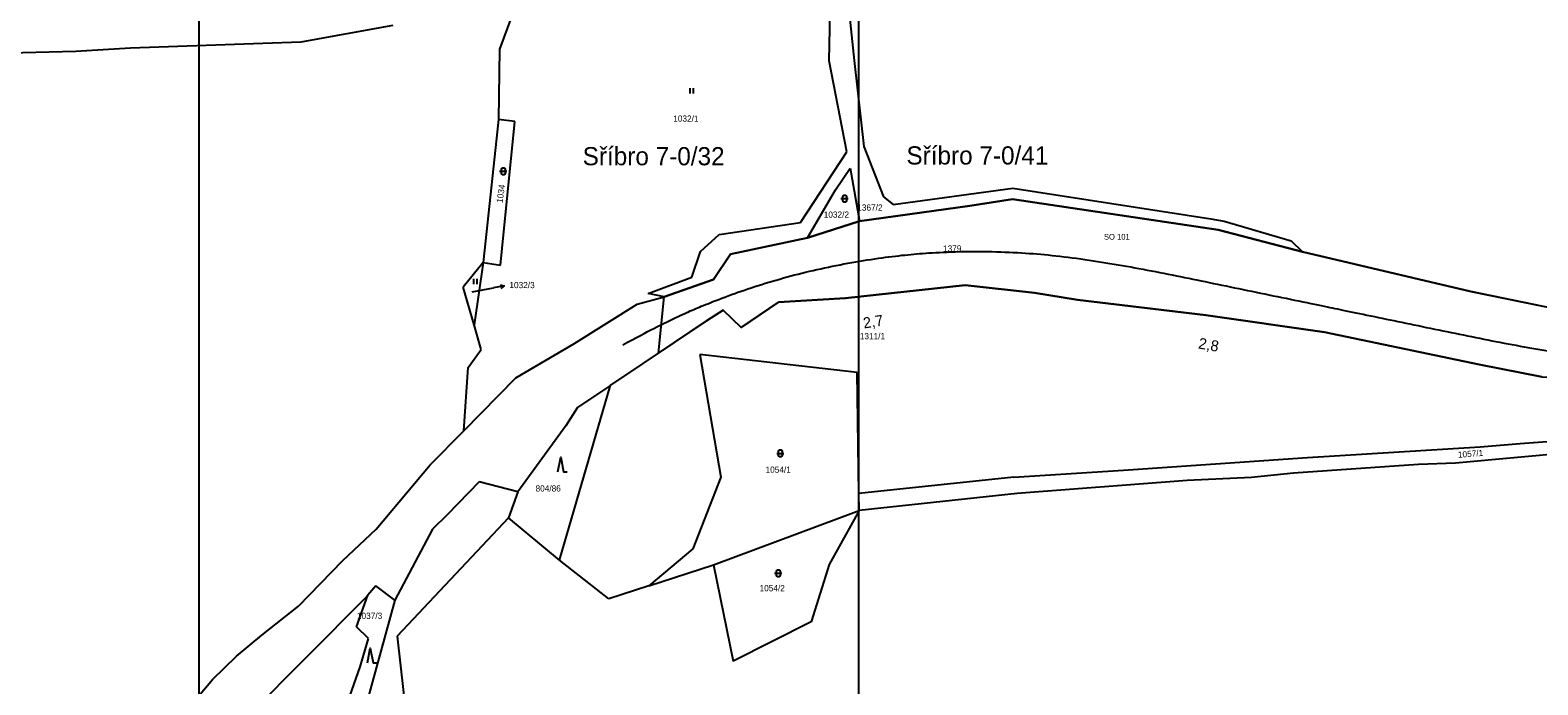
# Model space of a CAD drawing. Extents: x -852001 to -842497, y -1063614 to -1052182.
# Drawn here: x -843977.7 to -843563.3, y -1061386 to -1061205.9 of the extents above; entities that cross this region are included whole.
import ezdxf

# ---------------------------------------------------------------- set-up
doc = ezdxf.new("R2010")
doc.units = 0
for name, color, linetype in [('Default', 7, 'Continuous'), ('KLADY_ZMVM', 7, 'Continuous'), ('KN_HRANICE', 7, 'Continuous'), ('KN_KULTURY', 7, 'Continuous'), ('KN_PARCELY', 7, 'Continuous'), ('LEGENDA', 7, 'Continuous'), ('obvod_stavby', 7, 'Continuous'), ('so', 7, 'Continuous'), ('Vrstva 7', 7, 'Continuous'), ('Železniční svršek', 7, 'Continuous')]:
    doc.layers.add(name, color=color, linetype=linetype)

# ---------------------------------------------------------------- blocks, each defined once
blk = doc.blocks.new('306')
at = {"layer": 'Default'}
for p, q in [((-0.5, 1.5), (-0.5, 0)), ((0.5, 0), (0.5, 1.5))]:
    blk.add_line(p, q, dxfattribs=at)
blk = doc.blocks.new('308')
at = {"layer": 'Default'}
blk.add_lwpolyline([(-0.75, 0), (0, 4), (0.75, 0), (1.75, 0)], dxfattribs=at)
blk = doc.blocks.new('316')
at = {"layer": 'Default'}
for points in [[(-1, 1), (0.27, 1), (1, 1)], [(-0.5, 1.5), (-0.4, 1.79), (-0.15, 1.97), (0.16, 1.97), (0.41, 1.79), (0.51, 1.5), (0.51, 0.5), (0.41, 0.21), (0.16, 0.03), (-0.15, 0.03), (-0.4, 0.21), (-0.5, 0.5), (-0.5, 1.5)]]:
    blk.add_lwpolyline(points, dxfattribs=at)
blk = doc.blocks.new('10292')
at = {"layer": 'Default'}
blk.add_line((0, 3), (0, 0), dxfattribs=at)
blk.add_lwpolyline([(-0.5, 2), (0, 3), (0.5, 2)], dxfattribs=at)

msp = doc.modelspace()

# ---------------------------------------------------------------- linework, layer by layer
at = {"layer": 'KLADY_ZMVM'}
msp.add_line((-843750, -1061000), (-843750, -1061500), dxfattribs=at)
at = {"layer": 'KN_HRANICE'}
for p, q in [((-843758.11, -1061214.34), (-843757.44, -1061183.54)), ((-843842.44, -1061194.12), (-843848.69, -1061211.1)), ((-843752.83, -1061198.6), (-843751.24, -1061214.26)), ((-843878, -1061204.64), (-843903.31, -1061209.15)), ((-843903.31, -1061209.15), (-843950.16, -1061210.8)), ((-843965.16, -1061211.72), (-844011.33, -1061212.96)), ((-843950.16, -1061210.8), (-843965.16, -1061211.72)), ((-843848.69, -1061211.1), (-843848.99, -1061230.47)), ((-843753.24, -1061239.32), (-843758.11, -1061214.34)), ((-843751.24, -1061214.26), (-843748.59, -1061237.93)), ((-843848.99, -1061230.47), (-843853.2, -1061269.79)), ((-843844.45, -1061231.05), (-843848.99, -1061230.47)), ((-843848.42, -1061270.5), (-843844.45, -1061231.05)), ((-843748.59, -1061237.93), (-843743.16, -1061251.77)), ((-843765.97, -1061258.82), (-843753.24, -1061239.32)), ((-843756.33, -1061249.86), (-843752.32, -1061243.82)), ((-843752.32, -1061243.82), (-843749.69, -1061258.46)), ((-843763.99, -1061263.04), (-843756.33, -1061249.86)), ((-843740.51, -1061253.88), (-843707.55, -1061249.34)), ((-843707.55, -1061249.34), (-843653.11, -1061257.75)), ((-843749.69, -1061258.46), (-843719.38, -1061254.23)), ((-843743.16, -1061251.77), (-843740.51, -1061253.88)), ((-843719.38, -1061254.23), (-843707.71, -1061252.4)), ((-843707.71, -1061252.4), (-843651.14, -1061260.86)), ((-843788.34, -1061262.14), (-843765.97, -1061258.82)), ((-843763.99, -1061263.04), (-843749.69, -1061258.46)), ((-843653.11, -1061257.75), (-843649.46, -1061258.41)), ((-843649.46, -1061258.41), (-843631.1, -1061263.83)), ((-843793.44, -1061266.79), (-843788.34, -1061262.14)), ((-843785.22, -1061267.47), (-843763.99, -1061263.04)), ((-843651.14, -1061260.86), (-843627.97, -1061266.91)), ((-843795.86, -1061273.88), (-843793.44, -1061266.79)), ((-843631.1, -1061263.83), (-843627.97, -1061266.91)), ((-843627.97, -1061266.91), (-843581.64, -1061277.78)), ((-843853.2, -1061269.79), (-843858.65, -1061276.59)), ((-843853.2, -1061269.79), (-843855.66, -1061286.98)), ((-843853.2, -1061269.79), (-843848.42, -1061270.5)), ((-843789.91, -1061274.45), (-843785.22, -1061267.47)), ((-843807.87, -1061278.34), (-843795.86, -1061273.88)), ((-843803.41, -1061279.25), (-843789.91, -1061274.45)), ((-843855.66, -1061286.98), (-843858.65, -1061276.59)), ((-843810.84, -1061281.31), (-843803.41, -1061279.25)), ((-843803.41, -1061279.25), (-843807.87, -1061278.34)), ((-843753.6, -1061279.61), (-843772.02, -1061280.75)), ((-843720.66, -1061276.06), (-843753.6, -1061279.61)), ((-843701.61, -1061278.11), (-843720.66, -1061276.06)), ((-843689.83, -1061280.06), (-843701.61, -1061278.11)), ((-843581.64, -1061277.78), (-843550.13, -1061284.28)), ((-843828.23, -1061292.19), (-843810.84, -1061281.31)), ((-843787.23, -1061282.93), (-843791.76, -1061285.89)), ((-843782.31, -1061287.73), (-843787.23, -1061282.93)), ((-843772.02, -1061280.75), (-843782.31, -1061287.73)), ((-843654.49, -1061284.29), (-843689.83, -1061280.06)), ((-843853.72, -1061293.7), (-843855.66, -1061286.98)), ((-843791.76, -1061285.89), (-843818.17, -1061303.58)), ((-843621.95, -1061288.97), (-843654.49, -1061284.29)), ((-843579.4, -1061297.9), (-843621.95, -1061288.97)), ((-843857.29, -1061298.68), (-843853.72, -1061293.7)), ((-843844.22, -1061301.54), (-843828.23, -1061292.19)), ((-843750.4, -1061300.1), (-843793.61, -1061295.15)), ((-843793.61, -1061295.15), (-843787.86, -1061328.87)), ((-843858.52, -1061316.07), (-843857.29, -1061298.68)), ((-843749.88, -1061333.37), (-843750.4, -1061300.1)), ((-843562.17, -1061301.21), (-843579.4, -1061297.9)), ((-843858.52, -1061316.07), (-843844.22, -1061301.54)), ((-843832.24, -1061351.7), (-843818.17, -1061303.58)), ((-843818.41, -1061303.74), (-843827.22, -1061309.69)), ((-843818.17, -1061303.58), (-843818.41, -1061303.74)), ((-843827.22, -1061309.69), (-843830.42, -1061314.73)), ((-843867.78, -1061325.46), (-843858.52, -1061316.07)), ((-843830.42, -1061314.73), (-843843.69, -1061332.92)), ((-843626.56, -1061323.43), (-843579.08, -1061320.55)), ((-843579.08, -1061320.55), (-843568.11, -1061319.58)), ((-843568.11, -1061319.58), (-843556.99, -1061318.74)), ((-843677.18, -1061326.93), (-843626.56, -1061323.43)), ((-843585.86, -1061325.04), (-843596.03, -1061325.37)), ((-843552.81, -1061321.96), (-843585.86, -1061325.04)), ((-843882.65, -1061343.2), (-843867.78, -1061325.46)), ((-843787.86, -1061328.87), (-843795.52, -1061348.6)), ((-843707.33, -1061328.88), (-843749.88, -1061333.37)), ((-843707.33, -1061328.88), (-843677.18, -1061326.93)), ((-843641.98, -1061328.96), (-843659.64, -1061329.79)), ((-843630.42, -1061327.79), (-843641.98, -1061328.96)), ((-843596.03, -1061325.37), (-843630.42, -1061327.79)), ((-843854.29, -1061330.11), (-843863.1, -1061339.26)), ((-843843.69, -1061332.92), (-843854.29, -1061330.11)), ((-843843.69, -1061332.92), (-843846.21, -1061340.02)), ((-843749.81, -1061338.04), (-843749.88, -1061333.37)), ((-843706.37, -1061333.38), (-843749.81, -1061338.04)), ((-843659.64, -1061329.79), (-843706.37, -1061333.38)), ((-843846.21, -1061340.02), (-843876.82, -1061372.57)), ((-843863.1, -1061339.26), (-843867.1, -1061343.15)), ((-843832.24, -1061351.7), (-843846.21, -1061340.02)), ((-843789.86, -1061352.99), (-843749.81, -1061338.04)), ((-843749.81, -1061338.04), (-843758.11, -1061352.86)), ((-843891.79, -1061351.74), (-843882.65, -1061343.2)), ((-843867.1, -1061343.15), (-843877.51, -1061362.72)), ((-843795.52, -1061348.6), (-843807.69, -1061358.77)), ((-843903.92, -1061364.33), (-843891.79, -1061351.74)), ((-843818.66, -1061362.35), (-843832.24, -1061351.7)), ((-843807.69, -1061358.77), (-843789.86, -1061352.99)), ((-843789.86, -1061352.99), (-843784.44, -1061379.49)), ((-843758.11, -1061352.86), (-843763.06, -1061368.65)), ((-843885.63, -1061362.15), (-843917.63, -1061394.28)), ((-843887.98, -1061370.03), (-843884.91, -1061361.32)), ((-843884.91, -1061361.32), (-843885.63, -1061362.15)), ((-843882.66, -1061358.72), (-843884.91, -1061361.32)), ((-843877.51, -1061362.72), (-843882.66, -1061358.72)), ((-843807.69, -1061358.77), (-843818.66, -1061362.35)), ((-843914.06, -1061372.28), (-843903.92, -1061364.33)), ((-843877.51, -1061362.72), (-843889.86, -1061407.89)), ((-843884.73, -1061373.28), (-843887.98, -1061370.03)), ((-843763.06, -1061368.65), (-843784.44, -1061379.49)), ((-843921.04, -1061378.12), (-843914.06, -1061372.28)), ((-843886.98, -1061381.02), (-843884.73, -1061373.28)), ((-843876.82, -1061372.57), (-843870.39, -1061430.31)), ((-843927.56, -1061384.52), (-843921.04, -1061378.12)), ((-843890.35, -1061390.64), (-843886.98, -1061381.02)), ((-843945.96, -1061406.23), (-843927.56, -1061384.52))]:
    msp.add_line(p, q, dxfattribs=at)
at = {"layer": 'KN_PARCELY'}
msp.add_line((-843856.19, -1061277.9), (-843850.36, -1061276.81), dxfattribs=at)
at = {"layer": 'LEGENDA'}
msp.add_lwpolyline([(-843931.33, -1061576.22), (-843337.33, -1061576.22), (-843337.33, -1061156.22), (-843931.33, -1061156.22)], close=True, dxfattribs=at)
at = {"layer": 'obvod_stavby'}
msp.add_line((-843804.96, -1061294.74), (-843803.41, -1061279.25), dxfattribs=at)
for points in [[(-843536.01, -1061286.79), (-843550.13, -1061284.28), (-843581.64, -1061277.78), (-843627.97, -1061266.91), (-843651.14, -1061260.86), (-843707.71, -1061252.4), (-843719.38, -1061254.23), (-843749.69, -1061258.46), (-843763.99, -1061263.04), (-843785.22, -1061267.47), (-843789.91, -1061274.45), (-843803.41, -1061279.25)], [(-843804.96, -1061294.74), (-843791.76, -1061285.89), (-843787.23, -1061282.93), (-843782.31, -1061287.73), (-843772.02, -1061280.75), (-843753.6, -1061279.61), (-843720.66, -1061276.06), (-843701.61, -1061278.11), (-843689.83, -1061280.06), (-843654.49, -1061284.29), (-843621.95, -1061288.97), (-843579.4, -1061297.9), (-843562.17, -1061301.21), (-843550.96, -1061302.01), (-843541.07, -1061302.99)]]:
    msp.add_lwpolyline(points, dxfattribs=at)
at = {"layer": 'Železniční svršek'}
msp.add_open_spline([(-843814.8, -1061292.46), (-843807.55, -1061288.51), (-843800.05, -1061284.84), (-843795.59, -1061282.83), (-843792.03, -1061281.34), (-843784.97, -1061278.61), (-843777.74, -1061276.13), (-843769.61, -1061273.72), (-843761.54, -1061271.7), (-843752.93, -1061269.93), (-843744.31, -1061268.56), (-843737, -1061267.68), (-843731.14, -1061267.17), (-843722.35, -1061266.75), (-843713.28, -1061266.75), (-843703.86, -1061267.17), (-843695.99, -1061267.88), (-843686.54, -1061269.1), (-843677.48, -1061270.59), (-843668.34, -1061272.3), (-843659.18, -1061274.15), (-843650.24, -1061275.99), (-843640.69, -1061277.96), (-843631.28, -1061279.9), (-843622.03, -1061281.82), (-843617.49, -1061282.77), (-843609.21, -1061284.48), (-843600.78, -1061286.23), (-843591.65, -1061288.12), (-843582.54, -1061289.99), (-843573.66, -1061291.77), (-843564.83, -1061293.4), (-843556.32, -1061294.8), (-843547.97, -1061295.88), (-843539.88, -1061296.61), (-843532.11, -1061296.98), (-843523.63, -1061297.04), (-843515.26, -1061296.73), (-843507.43, -1061296.12), (-843502.84, -1061295.63), (-843494.35, -1061294.43), (-843485.91, -1061292.87), (-843478.02, -1061291.08), (-843469.68, -1061288.8)], degree=3, dxfattribs=at)

# ---------------------------------------------------------------- block references
at = {"layer": 'KN_KULTURY'}
for name, p in [('306', (-843795.91, -1061223.31)), ('316', (-843847.66, -1061245.71)), ('316', (-843753.83, -1061253.23)), ('306', (-843855.38, -1061275.76)), ('308', (-843831.87, -1061327.35)), ('316', (-843771.5, -1061323.33)), ('316', (-843772.08, -1061356.28)), ('308', (-843884.21, -1061379.89))]:
    msp.add_blockref(name, p, dxfattribs=at)
at = {"layer": 'KN_PARCELY', "rotation": -79.42256800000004}
msp.add_blockref('10292', (-843850.36, -1061276.81), dxfattribs=at)

# ---------------------------------------------------------------- texts
at = {"layer": 'KLADY_ZMVM'}
for s, p in [('Sříbro 7-0/32', (-843825.84, -1061243.06)), ('Sříbro 7-0/41', (-843736.84, -1061242.85))]:
    msp.add_text(s, height=5, dxfattribs=at).set_placement(p)
at = {"layer": 'KN_PARCELY'}
for s, height, p in [('1032/1', 1.7, (-843800.94, -1061231.07)), ('1367/2', 1.7, (-843750.35, -1061255.54)), ('1032/2', 1.7, (-843759.57, -1061257.48)), ('1379', 1.7, (-843726.78, -1061266.8)), ('1032/3', 1.7, (-843845.98, -1061276.86)), ('1032/3', 0.1, (-843856.49, -1061277.9)), ('1311/1', 1.7, (-843749.66, -1061290.91)), ('1054/1', 1.7, (-843775.56, -1061327.64)), ('804/86', 1.7, (-843838.79, -1061332.8)), ('1054/2', 1.7, (-843777.21, -1061360.24)), ('1037/3', 1.7, (-843887.89, -1061367.84))]:
    msp.add_text(s, height=height, dxfattribs=at).set_placement(p)
for s, rotation, p in [('1034', 81.933, (-843847.87, -1061253.49)), ('1057/1', 4.412, (-843585.17, -1061323.54))]:
    msp.add_text(s, height=1.7, rotation=rotation, dxfattribs=at).set_placement(p)
at = {"layer": 'so'}
msp.add_text('SO 101', height=1.567, dxfattribs=at).set_placement((-843682.55, -1061263.51))
at = {"layer": 'Vrstva 7'}
for s, rotation, p in [('2,7', 8.7076, (-843748.51, -1061287.97)), ('2,8', 350.2045, (-843656.75, -1061293.43))]:
    msp.add_text(s, height=3, rotation=rotation, dxfattribs=at).set_placement(p)

doc.saveas('drawing.dxf')
